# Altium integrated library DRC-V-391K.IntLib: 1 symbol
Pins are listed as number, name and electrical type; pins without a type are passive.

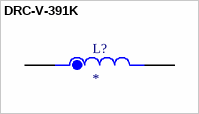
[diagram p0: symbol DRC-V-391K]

## DRC-V-391K
designator L?
Radial Coil Inductor; MF: Bel Fuse; MP: DRC-V-391K
footprint IND_DRC-V-391K
pins: 1, 2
